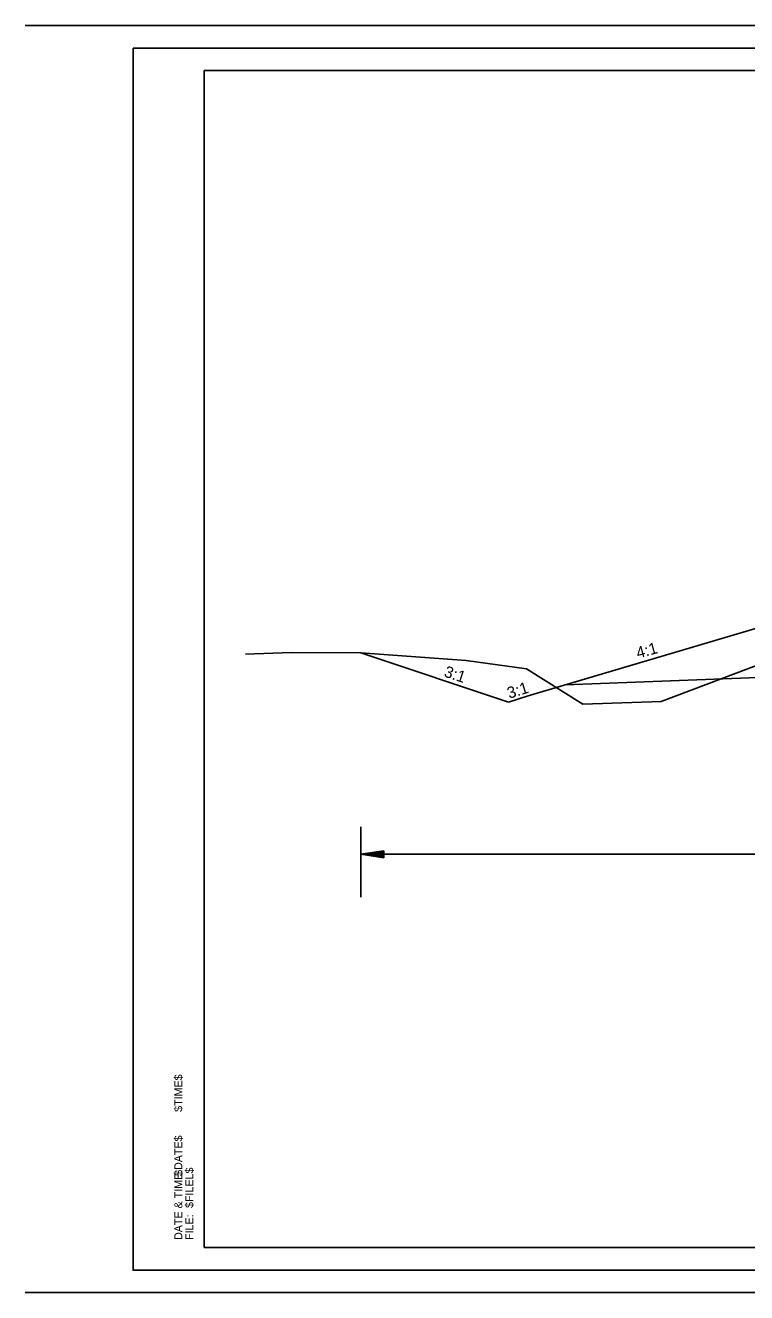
# Model space of a CAD drawing. Extents: x 6125 to 14104, y 8730 to 11067.
# Drawn here: x 8023 to 8652, y 9961 to 11067 of the extents above; entities that cross this region are included whole.
import ezdxf

# ---------------------------------------------------------------- set-up
doc = ezdxf.new("R2010")
doc.units = 0
for name, color, linetype in [('GREEN_TXT', 7, 'Continuous'), ('R_No Plot', 7, 'Continuous'), ('SEAL-INFO', 7, 'Continuous'), ('Stage 1 Construction', 7, 'Continuous')]:
    doc.layers.add(name, color=color, linetype=linetype)

msp = doc.modelspace()

# ---------------------------------------------------------------- linework, layer by layer
for p, q in [((8461.8, 10481.6), (8670.1, 10543.3)), ((8444.7, 10475.9), (8315.6, 10519)), ((8811.8, 10503.1), (8494.2, 10491.2)), ((8461.8, 10481.6), (8444.7, 10475.9))]:
    msp.add_line(p, q)
at = {"layer": 'GREEN_TXT'}
for p, q in [((9782.7, 11066.7), (8022.7, 11066.7)), ((8178.8, 11027.3), (9759.7, 11027.3)), ((8178.8, 10000), (8178.8, 11027.3)), ((9759.7, 10000), (8178.8, 10000)), ((8022.7, 9960.6), (9782.7, 9960.6))]:
    msp.add_line(p, q, dxfattribs=at)
at = {"layer": 'R_No Plot'}
msp.add_lwpolyline([(8214.9, 10518), (8254.7, 10519.4), (8315.6, 10519), (8407.7, 10512.2), (8460.4, 10505.1), (8509.6, 10474.3), (8577.8, 10476.5), (8706.5, 10525.2), (8791.8, 10534.6), (9005.6, 10537.5), (9218.9, 10534.6), (9305.3, 10526.2), (9403.9, 10495.9), (9428.2, 10465.3), (9480.8, 10463.7), (9510.7, 10505.5), (9538.9, 10523.9), (9588.8, 10533.2), (9678, 10524.6), (9750.8, 10523.3)], dxfattribs=at)
at = {"layer": 'SEAL-INFO'}
msp.add_lwpolyline([(8116.8, 11046.8), (9783.5, 11046.8), (9783.5, 9980.1), (8116.8, 9980.1)], close=True, dxfattribs=at)
at = {"layer": 'Stage 1 Construction'}
for p, q in [((8315.6, 10305.7), (8315.6, 10367.2)), ((8335.6, 10346.2), (8315.6, 10343.2)), ((8315.6, 10343.2), (9218.9, 10343.2)), ((8335.6, 10340.2), (8315.6, 10343.2)), ((8335.6, 10345.7), (8318.9, 10343.2)), ((8335.6, 10340.7), (8318.9, 10343.2)), ((8335.6, 10345.1), (8322.4, 10343.2)), ((8335.6, 10341.2), (8322.4, 10343.2)), ((8335.6, 10344.6), (8325.7, 10343.2)), ((8335.6, 10341.7), (8325.7, 10343.2)), ((8335.6, 10344.1), (8329.1, 10343.2)), ((8335.6, 10342.2), (8329.1, 10343.2)), ((8335.6, 10343.6), (8332.4, 10343.2)), ((8335.6, 10342.7), (8332.4, 10343.2)), ((8335.6, 10340.2), (8335.6, 10346.2))]:
    msp.add_line(p, q, dxfattribs=at)

# ---------------------------------------------------------------- texts
for s, height, p in [('$TIME$', 6.98, (8159.8, 10118.4)), ('$DATE$', 6.98, (8159.8, 10062.5)), ('DATE & TIME:', 6.984, (8159.8, 10006.6)), ('$FILEL$', 6.98, (8169.4, 10034.5)), ('FILE: ', 6.98, (8169.4, 10006.6))]:
    msp.add_text(s, height=height, rotation=90).set_placement(p)
for s, rotation, p in [('4:1', 15.3562, (8557.6, 10514)), ('3:1', 341.6876, (8387.6, 10498.5)), ('3:1', 17.2581, (8445.2, 10478.9))]:
    msp.add_text(s, height=10, rotation=rotation, dxfattribs=at).set_placement(p)

doc.saveas('drawing.dxf')
